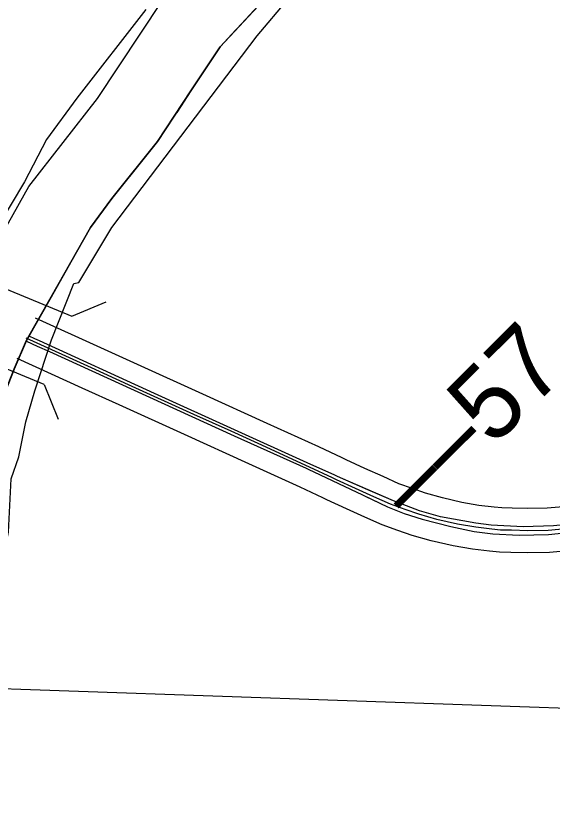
# Model space of a CAD drawing. Extents: x -132.8 to -73.3, y -60 to -26.
# Drawn here: x -126.349 to -125.624, y -53.272 to -52.198 of the extents above; entities that cross this region are included whole.
import ezdxf

# ---------------------------------------------------------------- set-up
doc = ezdxf.new("R2010")
doc.units = 0
for name, color, linetype in [('tdCoClipBndry', 7, 'Continuous'), ('tdCoCoBndry', 7, 'Continuous'), ('tdCoCorpBndry', 7, 'Continuous'), ('tdCoDivCarto', 7, 'Continuous'), ('tdCoHydroRiver', 7, 'Continuous'), ('tdCoPriCL', 7, 'Continuous'), ('tdCoPriDiv', 7, 'Continuous'), ('tdCoPrimary', 7, 'Continuous'), ('tdCoSectLine', 7, 'Continuous'), ('tdCoSectLinePart', 7, 'Continuous'), ('tdCoStBndry', 7, 'Continuous'), ('tdCoStBndryPart', 7, 'Continuous'), ('tdCoStrucDivPri', 7, 'Continuous'), ('tdCoTwpBndryShd', 7, 'Continuous'), ('tdStHwyPriRefPost1', 7, 'Continuous')]:
    doc.layers.add(name, color=color, linetype=linetype)

msp = doc.modelspace()

# ---------------------------------------------------------------- linework, layer by layer
at = {"layer": 'tdCoClipBndry'}
msp.add_lwpolyline([(-126.5464, -53.2761), (-126.5467, -53.1011), (-126.535, -52.9749), (-126.5, -52.8084), (-126.4719, -52.7078), (-126.4273, -52.599), (-126.3317, -52.4289), (-126.2389, -52.3097), (-126.1519, -52.1784), (-126.0448, -52.0608), (-125.9178, -51.9081), (-125.8097, -51.7219), (-125.699, -51.5184), (-125.6517, -51.3639)], dxfattribs=at)
at = {"layer": 'tdCoCoBndry'}
for p, q in [((-126.0727, -52.2398), (-126.0152, -52.1779)), ((-126.112, -52.2995), (-126.0727, -52.2398)), ((-126.1573, -52.3681), (-126.112, -52.2995)), ((-126.2192, -52.4452), (-126.1573, -52.3681)), ((-126.2482, -52.4844), (-126.2192, -52.4452)), ((-126.3011, -52.578), (-126.2482, -52.4844)), ((-126.3345, -52.637), (-126.3011, -52.578)), ((-126.3511, -52.6756), (-126.3345, -52.637))]:
    msp.add_line(p, q, dxfattribs=at)
for points in [[(-126.0156, -52.1779), (-126.073, -52.2398), (-126.1124, -52.2995), (-126.1576, -52.3681), (-126.2195, -52.4452), (-126.2486, -52.4844), (-126.3015, -52.578), (-126.3349, -52.637), (-126.3515, -52.6756), (-126.3774, -52.7403), (-126.4021, -52.829), (-126.4228, -52.9337), (-126.4361, -52.9898), (-126.4436, -53.0427), (-126.4468, -53.1057), (-126.4467, -53.2692), (-126.429, -53.3962)], [(-126.4286, -53.3962), (-126.4463, -53.2692), (-126.4464, -53.1057), (-126.4433, -53.0427), (-126.4357, -52.9898), (-126.4224, -52.9337), (-126.4018, -52.829), (-126.377, -52.7403), (-126.3511, -52.6756), (-126.3345, -52.637), (-126.3011, -52.578), (-126.2482, -52.4844), (-126.2192, -52.4452), (-126.1573, -52.3681), (-126.112, -52.2995), (-126.0727, -52.2398), (-126.0152, -52.1779)]]:
    msp.add_lwpolyline(points, dxfattribs=at)
at = {"layer": 'tdCoCorpBndry'}
msp.add_lwpolyline([(-126.4286, -53.3962), (-126.4463, -53.2692), (-126.4464, -53.1057), (-126.4433, -53.0427), (-126.4357, -52.9898), (-126.4224, -52.9337), (-126.4018, -52.829), (-126.377, -52.7403), (-126.3511, -52.6756), (-126.3345, -52.637), (-126.3011, -52.578), (-126.2482, -52.4844), (-126.2192, -52.4452), (-126.1573, -52.3681), (-126.112, -52.2995), (-126.0727, -52.2398), (-126.0152, -52.1779)], dxfattribs=at)
at = {"layer": 'tdCoDivCarto'}
for p, q in [((-126.3237, -52.6351), (-126.3314, -52.6316)), ((-126.3174, -52.638), (-126.3237, -52.6351)), ((-126.335, -52.6382), (-126.3204, -52.6449)), ((-126.335, -52.6382), (-126.3204, -52.6449)), ((-126.3204, -52.6449), (-126.304, -52.6524)), ((-126.1618, -52.7091), (-126.3174, -52.638)), ((-126.304, -52.6524), (-126.0538, -52.7664)), ((-125.95, -52.8052), (-126.1618, -52.7091)), ((-126.0538, -52.7664), (-125.9565, -52.8102)), ((-125.9188, -52.8193), (-125.95, -52.8052)), ((-125.9188, -52.8193), (-125.95, -52.8052)), ((-125.9565, -52.8102), (-125.9538, -52.8115)), ((-125.9538, -52.8115), (-125.8803, -52.8464)), ((-125.9149, -52.8211), (-125.9188, -52.8193)), ((-125.9149, -52.8211), (-125.9188, -52.8193)), ((-125.9099, -52.8234), (-125.9149, -52.8211)), ((-125.8729, -52.8396), (-125.9099, -52.8234)), ((-125.8383, -52.8546), (-125.8729, -52.8396)), ((-125.8803, -52.8464), (-125.8768, -52.8481)), ((-125.8768, -52.8481), (-125.8466, -52.8623)), ((-125.8033, -52.8678), (-125.8383, -52.8546)), ((-125.8466, -52.8623), (-125.8238, -52.8716)), ((-125.8238, -52.8716), (-125.7997, -52.8793)), ((-125.7745, -52.876), (-125.8033, -52.8678)), ((-125.7997, -52.8793), (-125.7608, -52.8892)), ((-125.7268, -52.8848), (-125.7745, -52.876)), ((-125.7608, -52.8892), (-125.729, -52.8958)), ((-125.7062, -52.8873), (-125.7268, -52.8848)), ((-125.6629, -52.8894), (-125.7062, -52.8873)), ((-125.6218, -52.8884), (-125.6629, -52.8894)), ((-125.729, -52.8958), (-125.7041, -52.8993)), ((-125.7041, -52.8993), (-125.6681, -52.9007)), ((-125.6681, -52.9007), (-125.6284, -52.8999)), ((-125.6284, -52.8999), (-125.5939, -52.8963))]:
    msp.add_line(p, q, dxfattribs=at)
for points in [[(-126.3174, -52.638), (-126.3237, -52.6351), (-126.3314, -52.6316)], [(-126.3174, -52.638), (-126.3237, -52.6351), (-126.3314, -52.6316)], [(-126.3174, -52.638), (-126.3237, -52.6351), (-126.3314, -52.6316)], [(-126.335, -52.6382), (-126.3204, -52.6449)], [(-126.335, -52.6382), (-126.3204, -52.6449)], [(-126.3204, -52.6449), (-126.304, -52.6524), (-126.0538, -52.7664), (-125.9565, -52.8102), (-125.9538, -52.8115)], [(-126.3204, -52.6449), (-126.304, -52.6524), (-126.0538, -52.7664), (-125.9565, -52.8102), (-125.9538, -52.8115)], [(-126.3204, -52.6449), (-126.304, -52.6524), (-126.0538, -52.7664), (-125.9565, -52.8102), (-125.9538, -52.8115)], [(-125.95, -52.8052), (-126.1618, -52.7091), (-126.3174, -52.638)], [(-125.95, -52.8052), (-126.1618, -52.7091), (-126.3174, -52.638)], [(-125.95, -52.8052), (-126.1618, -52.7091), (-126.3174, -52.638)], [(-125.9188, -52.8193), (-125.95, -52.8052)], [(-125.9188, -52.8193), (-125.95, -52.8052)], [(-125.9538, -52.8115), (-125.8803, -52.8464), (-125.8466, -52.8623), (-125.8238, -52.8716), (-125.7997, -52.8793), (-125.7608, -52.8892), (-125.729, -52.8958), (-125.7041, -52.8993), (-125.6681, -52.9007), (-125.6284, -52.8999), (-125.5939, -52.8963), (-125.5577, -52.89), (-125.5232, -52.8807), (-125.4779, -52.8645), (-125.4481, -52.8519)], [(-125.9538, -52.8115), (-125.8803, -52.8464), (-125.8466, -52.8623), (-125.8238, -52.8716), (-125.7997, -52.8793), (-125.7608, -52.8892), (-125.729, -52.8958), (-125.7041, -52.8993), (-125.6681, -52.9007), (-125.6284, -52.8999), (-125.5939, -52.8963), (-125.5577, -52.89), (-125.5232, -52.8807), (-125.4779, -52.8645), (-125.4481, -52.8519)], [(-125.9538, -52.8115), (-125.8803, -52.8464), (-125.8768, -52.8481)], [(-125.9149, -52.8211), (-125.9188, -52.8193)], [(-125.9149, -52.8211), (-125.9188, -52.8193)], [(-125.4517, -52.8433), (-125.4999, -52.8634), (-125.527, -52.8722), (-125.5566, -52.8785), (-125.5889, -52.8851), (-125.6218, -52.8884), (-125.6629, -52.8894), (-125.7062, -52.8873), (-125.7268, -52.8848), (-125.7745, -52.876), (-125.8033, -52.8678), (-125.8383, -52.8546), (-125.9099, -52.8234), (-125.9149, -52.8211)], [(-125.4517, -52.8433), (-125.4999, -52.8634), (-125.527, -52.8722), (-125.5566, -52.8785), (-125.5889, -52.8851), (-125.6218, -52.8884), (-125.6629, -52.8894), (-125.7062, -52.8873), (-125.7268, -52.8848), (-125.7745, -52.876), (-125.8033, -52.8678), (-125.8383, -52.8546), (-125.9099, -52.8234), (-125.9149, -52.8211)], [(-125.8729, -52.8396), (-125.9099, -52.8234), (-125.9149, -52.8211)], [(-125.4517, -52.8433), (-125.4999, -52.8634), (-125.527, -52.8722), (-125.5566, -52.8785), (-125.5889, -52.8851), (-125.6218, -52.8884), (-125.6629, -52.8894), (-125.7062, -52.8873), (-125.7268, -52.8848), (-125.7745, -52.876), (-125.8033, -52.8678), (-125.8383, -52.8546), (-125.8729, -52.8396)], [(-125.8768, -52.8481), (-125.8466, -52.8623), (-125.8238, -52.8716), (-125.7997, -52.8793), (-125.7608, -52.8892), (-125.729, -52.8958), (-125.7041, -52.8993), (-125.6681, -52.9007), (-125.6284, -52.8999), (-125.5939, -52.8963), (-125.5577, -52.89), (-125.5232, -52.8807), (-125.4779, -52.8645), (-125.4481, -52.8519)]]:
    msp.add_lwpolyline(points, dxfattribs=at)
at = {"layer": 'tdCoHydroRiver'}
for points in [[(-126.4146, -53.345), (-126.4156, -53.2677), (-126.4133, -53.132), (-126.4049, -53.0581), (-126.3739, -52.9691), (-126.3593, -52.8969), (-126.3556, -52.8244), (-126.3453, -52.7947), (-126.3361, -52.7476), (-126.3239, -52.7054), (-126.3014, -52.6366), (-126.2708, -52.5602), (-126.2644, -52.5588), (-126.2197, -52.4843), (-126.0229, -52.2248), (-125.8972, -52.0754)], [(-126.1735, -52.189), (-126.2668, -52.3094), (-126.3079, -52.365), (-126.3379, -52.4226), (-126.4075, -52.5389), (-126.4309, -52.584), (-126.4612, -52.6494), (-126.5023, -52.7634), (-126.5182, -52.8229), (-126.5228, -52.8733), (-126.5302, -52.9141), (-126.5392, -53.2862)]]:
    msp.add_lwpolyline(points, dxfattribs=at)
at = {"layer": 'tdCoPriCL'}
msp.add_lwpolyline([(-125.6053, -52.8925), (-125.6288, -52.8944), (-125.6567, -52.8949), (-125.6785, -52.8942), (-125.6933, -52.8939), (-125.7052, -52.8928), (-125.7269, -52.8902), (-125.7519, -52.8861), (-125.7796, -52.8795), (-125.8041, -52.8726), (-125.8225, -52.8661), (-125.8424, -52.859), (-125.8648, -52.849), (-125.8896, -52.8379), (-125.9154, -52.8261), (-125.921, -52.8233), (-125.952, -52.8087), (-126.0217, -52.7768), (-126.0581, -52.7603), (-126.1086, -52.7375), (-126.1972, -52.6972), (-126.247, -52.6745), (-126.3353, -52.6343)], dxfattribs=at)
at = {"layer": 'tdCoPriDiv'}
for points in [[(-125.6085, -52.8627), (-125.6303, -52.8644), (-125.6565, -52.8649), (-125.6777, -52.8642), (-125.6916, -52.8639), (-125.7022, -52.863), (-125.7227, -52.8605), (-125.746, -52.8567), (-125.7721, -52.8505), (-125.795, -52.8439), (-125.8125, -52.8378), (-125.8312, -52.8312), (-125.8525, -52.8216), (-125.8772, -52.8105), (-125.9025, -52.799), (-125.9079, -52.7963), (-125.9394, -52.7815), (-126.0093, -52.7495), (-126.0962, -52.7101), (-126.1848, -52.6699), (-126.2346, -52.6472), (-126.3228, -52.607)], [(-125.6022, -52.9223), (-125.6273, -52.9244), (-125.6569, -52.9249), (-125.6794, -52.9242), (-125.6949, -52.9239), (-125.7083, -52.9227), (-125.7312, -52.92), (-125.7578, -52.9155), (-125.7872, -52.9085), (-125.8131, -52.9012), (-125.8325, -52.8944), (-125.8536, -52.8869), (-125.8771, -52.8763), (-125.9019, -52.8652), (-125.9284, -52.8531), (-125.9341, -52.8503), (-125.9646, -52.836), (-126.0342, -52.8041), (-126.121, -52.7648), (-126.2097, -52.7245), (-126.2595, -52.7018), (-126.3477, -52.6616)]]:
    msp.add_lwpolyline(points, dxfattribs=at)
at = {"layer": 'tdCoPrimary'}
for p, q in [((-126.335, -52.6382), (-126.3204, -52.6449)), ((-126.335, -52.6382), (-126.3204, -52.6449)), ((-125.9188, -52.8193), (-125.95, -52.8052)), ((-125.9188, -52.8193), (-125.95, -52.8052)), ((-125.9149, -52.8211), (-125.9188, -52.8193)), ((-125.9149, -52.8211), (-125.9188, -52.8193))]:
    msp.add_line(p, q, dxfattribs=at)
for points in [[(-126.3174, -52.638), (-126.3237, -52.6351), (-126.3314, -52.6316)], [(-126.3174, -52.638), (-126.3237, -52.6351), (-126.3314, -52.6316)], [(-125.6218, -52.8884), (-125.6629, -52.8894), (-125.7062, -52.8873), (-125.7268, -52.8848), (-125.7745, -52.876), (-125.8033, -52.8678), (-125.8383, -52.8546), (-125.8729, -52.8396), (-125.9099, -52.8234), (-125.9149, -52.8211), (-125.9188, -52.8193), (-125.95, -52.8052), (-126.1618, -52.7091), (-126.3174, -52.638), (-126.3237, -52.6351), (-126.3314, -52.6316)], [(-126.335, -52.6382), (-126.3204, -52.6449), (-126.304, -52.6524), (-126.0538, -52.7664), (-125.9565, -52.8102), (-125.9538, -52.8115), (-125.8803, -52.8464), (-125.8768, -52.8481), (-125.8466, -52.8623), (-125.8238, -52.8716), (-125.7997, -52.8793), (-125.7608, -52.8892), (-125.729, -52.8958), (-125.7041, -52.8993), (-125.6681, -52.9007), (-125.6284, -52.8999), (-125.5939, -52.8963)], [(-126.3204, -52.6449), (-126.304, -52.6524), (-126.0538, -52.7664), (-125.9565, -52.8102), (-125.9538, -52.8115)], [(-126.3204, -52.6449), (-126.304, -52.6524), (-126.0538, -52.7664), (-125.9565, -52.8102), (-125.9538, -52.8115)], [(-125.95, -52.8052), (-126.1618, -52.7091), (-126.3174, -52.638)], [(-125.95, -52.8052), (-126.1618, -52.7091), (-126.3174, -52.638)], [(-125.9538, -52.8115), (-125.8803, -52.8464), (-125.8768, -52.8481)], [(-125.9538, -52.8115), (-125.8803, -52.8464), (-125.8768, -52.8481)], [(-125.8729, -52.8396), (-125.9099, -52.8234), (-125.9149, -52.8211)], [(-125.8729, -52.8396), (-125.9099, -52.8234), (-125.9149, -52.8211)], [(-125.4517, -52.8433), (-125.4999, -52.8634), (-125.527, -52.8722), (-125.5566, -52.8785), (-125.5889, -52.8851), (-125.6218, -52.8884), (-125.6629, -52.8894), (-125.7062, -52.8873), (-125.7268, -52.8848), (-125.7745, -52.876), (-125.8033, -52.8678), (-125.8383, -52.8546), (-125.8729, -52.8396)], [(-125.4517, -52.8433), (-125.4999, -52.8634), (-125.527, -52.8722), (-125.5566, -52.8785), (-125.5889, -52.8851), (-125.6218, -52.8884), (-125.6629, -52.8894), (-125.7062, -52.8873), (-125.7268, -52.8848), (-125.7745, -52.876), (-125.8033, -52.8678), (-125.8383, -52.8546), (-125.8729, -52.8396)], [(-125.8768, -52.8481), (-125.8466, -52.8623), (-125.8238, -52.8716), (-125.7997, -52.8793), (-125.7608, -52.8892), (-125.729, -52.8958), (-125.7041, -52.8993), (-125.6681, -52.9007), (-125.6284, -52.8999), (-125.5939, -52.8963), (-125.5577, -52.89), (-125.5232, -52.8807), (-125.4779, -52.8645), (-125.4481, -52.8519)], [(-125.8768, -52.8481), (-125.8466, -52.8623), (-125.8238, -52.8716), (-125.7997, -52.8793), (-125.7608, -52.8892), (-125.729, -52.8958), (-125.7041, -52.8993), (-125.6681, -52.9007), (-125.6284, -52.8999), (-125.5939, -52.8963), (-125.5577, -52.89), (-125.5232, -52.8807), (-125.4779, -52.8645), (-125.4481, -52.8519)]]:
    msp.add_lwpolyline(points, dxfattribs=at)
at = {"layer": 'tdCoSectLine'}
for points in [[(-125.9694, -52.1265), (-126.0156, -52.1779), (-126.073, -52.2398), (-126.1124, -52.2995), (-126.1576, -52.3681), (-126.2195, -52.4452), (-126.2486, -52.4844), (-126.3015, -52.578), (-126.3349, -52.637), (-126.3515, -52.6756), (-126.3774, -52.7403), (-126.4021, -52.829), (-126.4228, -52.9337), (-126.4361, -52.9898), (-126.4436, -53.0427), (-126.4468, -53.1057)], [(-126.4468, -53.1057), (-124.9921, -53.1562)]]:
    msp.add_lwpolyline(points, dxfattribs=at)
at = {"layer": 'tdCoSectLinePart'}
for points in [[(-126.0515, -52.2166), (-126.073, -52.2398), (-126.1124, -52.2995), (-126.1317, -52.3288)], [(-126.172, -52.3861), (-126.2195, -52.4452), (-126.2486, -52.4844), (-126.3015, -52.578), (-126.3349, -52.637), (-126.3515, -52.6756), (-126.3774, -52.7403), (-126.4007, -52.8239)]]:
    msp.add_lwpolyline(points, dxfattribs=at)
at = {"layer": 'tdCoStBndry'}
msp.add_lwpolyline([(-126.0156, -52.1779), (-126.073, -52.2398), (-126.1124, -52.2995), (-126.1576, -52.3681), (-126.2195, -52.4452), (-126.2486, -52.4844), (-126.3015, -52.578), (-126.3349, -52.637), (-126.3515, -52.6756), (-126.3774, -52.7403), (-126.4021, -52.829), (-126.4228, -52.9337), (-126.4361, -52.9898), (-126.4436, -53.0427), (-126.4468, -53.1057), (-126.4467, -53.2692), (-126.429, -53.3962)], dxfattribs=at)
at = {"layer": 'tdCoStBndryPart'}
for points in [[(-126.0515, -52.2166), (-126.073, -52.2398), (-126.1124, -52.2995), (-126.1317, -52.3288)], [(-126.172, -52.3861), (-126.2195, -52.4452), (-126.2486, -52.4844), (-126.3015, -52.578), (-126.3349, -52.637), (-126.3515, -52.6756), (-126.3774, -52.7403), (-126.4007, -52.8239)]]:
    msp.add_lwpolyline(points, dxfattribs=at)
at = {"layer": 'tdCoStrucDivPri'}
for p, q in [((-126.3708, -52.564), (-126.2737, -52.6044)), ((-126.2737, -52.6044), (-126.2271, -52.5851)), ((-126.3112, -52.6971), (-126.4085, -52.6566)), ((-126.3112, -52.6971), (-126.292, -52.7437))]:
    msp.add_line(p, q, dxfattribs=at)
at = {"layer": 'tdCoTwpBndryShd'}
msp.add_lwpolyline([(-126.429, -53.3962), (-126.4467, -53.2692), (-126.4468, -53.1057), (-126.4436, -53.0427), (-126.4361, -52.9898), (-126.4228, -52.9337), (-126.4021, -52.829), (-126.3774, -52.7403), (-126.3515, -52.6756), (-126.3349, -52.637), (-126.3015, -52.578), (-126.2486, -52.4844), (-126.2195, -52.4452), (-126.1576, -52.3681), (-126.1124, -52.2995), (-126.073, -52.2398), (-126.0156, -52.1779)], dxfattribs=at)

# ---------------------------------------------------------------- texts
at = {"layer": 'tdStHwyPriRefPost1'}
msp.add_text('‒‒57', height=0.1, rotation=45, dxfattribs=at).set_placement((-125.8087, -52.8876))

doc.saveas('drawing.dxf')
